// Mitsubishi GX Works2 project: 1口   6B  9A   PLC: FX3U/FX3UC

PROGRAM MAIN
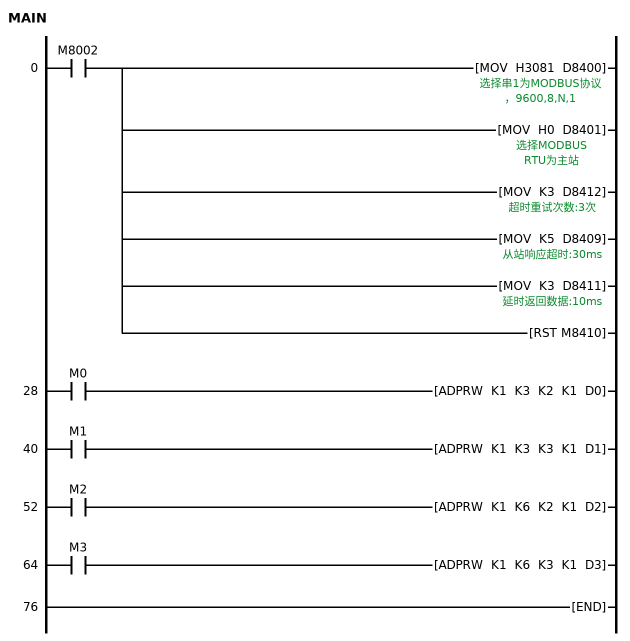
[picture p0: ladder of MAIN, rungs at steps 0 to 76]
0     LD      M8002
      MOV     H3081 D8400  ; 选择串1为MODBUS协议，9600,8,N,1
      MOV     H0 D8401  ; 选择MODBUS RTU为主站
      MOV     K3 D8412  ; 超时重试次数:3次
      MOV     K5 D8409  ; 从站响应超时:30ms
      MOV     K3 D8411  ; 延时返回数据:10ms
      RST     M8410
28    LD      M0
      ADPRW   K1 K3 K2 K1 D0
40    LD      M1
      ADPRW   K1 K3 K3 K1 D1
52    LD      M2
      ADPRW   K1 K6 K2 K1 D2
64    LD      M3
      ADPRW   K1 K6 K3 K1 D3
76    END
END_PROGRAM
